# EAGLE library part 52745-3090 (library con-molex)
FFC/FPC-to-Board 0.50mm (.020") SMT Top Contact Right Angle, ZIF, Style Receptacle 52745 / 52435 Source: http://www.molex.com/product/ffc/52745.html
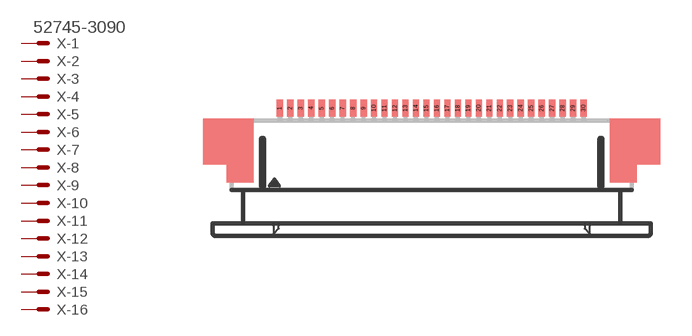
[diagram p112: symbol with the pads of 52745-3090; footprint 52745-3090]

Designator prefix X; gates -1=MV -2=M -3=M -4=M -5=M -6=M -7=M -8=M -9=M -10=M -11=M -12=M -13=M -14=M -15=M -16=M -17=M -18=M -19=M -20=M -21=M -22=M -23=M -24=M -25=M -26=M -27=M -28=M -29=M -30=M

## 52745-3090 (OC_FARNELL: unknown; OC_NEWARK: unknown)  [52745-3090]
1  -1:S  pas
2  -2:S  pas
3  -3:S  pas
4  -4:S  pas
5  -5:S  pas
6  -6:S  pas
7  -7:S  pas
8  -8:S  pas
9  -9:S  pas
10  -10:S  pas
11  -11:S  pas
12  -12:S  pas
13  -13:S  pas
14  -14:S  pas
15  -15:S  pas
16  -16:S  pas
17  -17:S  pas
18  -18:S  pas
19  -19:S  pas
20  -20:S  pas
21  -21:S  pas
22  -22:S  pas
23  -23:S  pas
24  -24:S  pas
25  -25:S  pas
26  -26:S  pas
27  -27:S  pas
28  -28:S  pas
29  -29:S  pas
30  -30:S  pas

## Footprint 52745-3090 (pad centres in mm)
FFC/FPC-to-Board 0.50mm (.020") SMT Top Contact Right Angle, ZIF, Style Receptacle 52745 / 52435 Source: http://www.molex.com/product/ffc/52745.html
smd 0.3 x 0.8: 1 -7.25,2.5; 2 -6.75,2.5; 3 -6.25,2.5; 4 -5.75,2.5; 5 -5.25,2.5; 6 -4.75,2.5; 7 -4.25,2.5; 8 -3.75,2.5; 9 -3.25,2.5; 10 -2.75,2.5; 11 -2.25,2.5; 12 -1.75,2.5; 13 -1.25,2.5; 14 -0.75,2.5; 15 -0.25,2.5; 16 0.25,2.5; 17 0.75,2.5; 18 1.25,2.5; 19 1.75,2.5; 20 2.25,2.5; 21 2.75,2.5; 22 3.25,2.5; 23 3.75,2.5; 24 4.25,2.5; 25 4.75,2.5; 26 5.25,2.5; 27 5.75,2.5; 28 6.25,2.5; 29 6.75,2.5; 30 7.25,2.5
